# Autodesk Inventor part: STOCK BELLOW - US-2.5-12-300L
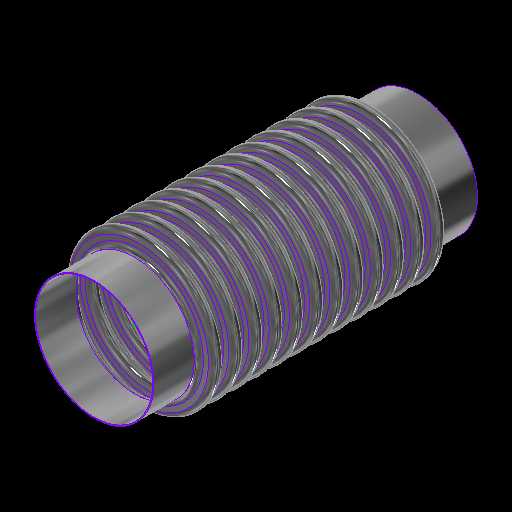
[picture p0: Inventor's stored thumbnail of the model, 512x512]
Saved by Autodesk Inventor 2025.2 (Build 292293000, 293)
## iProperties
Category: 24 GA (0.024 THICK)
RuleStatus: InUse
Created: 2024-01
Part Number: STOCK BELLOW - US-2.5-12-300L
Project: =STOCK BELLOWS: <Stock Number><SFILL>
Material: ASTM A240-304
Description: =STOCK BELLOWS: <Stock Number>, <SID_> I.D., <SOD_> O.D., <SPLY_> PLY, <Category>, <SNET_CONS> CONS.<PITCH_><STANGENT_> TANGENT<SFILL>
Document SubType Name: Sheet Metal
Designer: GS
Stock Number: U.S-2.5-12-300L
Surface Area: 1910.87 cm^2
Volume: 57.9833 cm^3
Sheet Metal Rule: Default
Appearance: STAINLESS STEEL
Mass: 467.188 g
Density: 8.05729 g/cm^3
THK: 0.036
ID: 3.500
OD: 4.250
CONS_: 2
PITCH: 0.500
TANGENT: 0.500
BELLOWS_UPSET: 0.000
d79: 1.000
d82: 1.000
d83: 26.000
d84: 24.000
d174: 8
d214: 8
STHK_: 0.024
SID_: 2.900
SOD_: 3.700
SPITCH_: 0.500
STANGENT__: 1.000
SBELLOWS_UPSET_: 0.000
SDIFF_TAN: 1.000
d252: 2
d275: 2
d287: 0.050
d289: 0.500
d290: 0.000
SOD_NECK: 2 15/16
PLY: 1
PSET: 4.178
PBAR: 1.035
COUNTER: 1.500
NET_TUBE: 3.071
CONS: 2
S_CONS: 0
NET_CONS: 2
ID_M: 88.90 mm
OD_M: 107.95 mm
THK_M: 0.91 mm
ID_U: 3.500 in
OD_U: 4.250 in
THK_U: 0.036 in
TANGENT2: 0.500
TAN_TO_TAN: 1.000 in
d80: 2.571
d81: 10
SID: 2.375
SCONS_: 12
SPITCH: 0.250
STANGENT_: 1.000
SBELLOWS_UPSET: 0.000
SNET_CONS: 12
SS_CONS: 0
SCONS: 8
d190: 8
d191: 1
d192: 1
d193: 8
d194: 0
SIZE: 2.50
PRESSURE: 300
d230: 8
STANGENT: 4.000
SPLY_: 1
d233: 8
d234: 0
d263: 2
d265: 1
d268: 2
d269: 0
d286: 2
d288: 1
d291: 2
d292: 0
SREROLL: 0.750
BLETP: 1.000 ul
PRES_Copy: 85
MATTABLE: 20 GA (0.036 THICK)
PART_NUMBER: U.S-2.5-12-300L
PITCH_: =, <SPITCH_> PITCH,
CFILL: .
SFILL: .
MESH: ,
COMP: 0.89
EXT: 0.45
LAT: 0.52
ANG: 573
ASR: 961
LSR: 436
ANSR: 35
PRES: 300
COMPM: 8.9
EXTM: 4.45
LATM: 5.20
ASRM: 168.300
PRESM: 20.684
LSRM: 76.357
ANSRM: 6.13
TEMPMIN: 20
TEMPMAX: 800
TEMPMINM: -7
TEMPMAXM: 427
WEIGHTM: 0.467
WEIGHT: 1.030
Author: GS
Keywords: 20 GA (0.036 THICK)
Comments: =STOCK BELLOW - <STOCK NUMBER>
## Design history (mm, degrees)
sketch "Sketch2"
  geometry: L1 (0, -177.245)-(0, 562.856) reference; L2 (45.364, 0)-(44.45, 0); L3 (48.082, -2.718)-(50.343, -2.718); L4 (48.082, -3.632)-(50.343, -3.632); L5 (50.343, -9.982)-(48.082, -9.982); L6 (50.343, -9.068)-(48.082, -9.068); L7 (45.364, -12.7)-(44.45, -12.7); L8 (48.082, 0)-(48.082, -12.7); L9 (50.343, -6.35)-(53.975, -6.35); L10 (44.45, 0)-(44.45, -12.7); L11 (20.376, 102.841)-(20.376, 101.926); L12 (58.262, 457.127)-(58.262, 349.177); L13 (58.262, 444.427)-(58.262, 336.477); L14 (93.133, -58.817)-(93.133, -71.517); L15 (118.746, -66.401)-(118.746, -66.401); L16 (50.343, -9.068)-(50.343, -9.982); L17 (48.082, -9.068)-(48.082, -9.982); L18 (48.082, -9.525)-(50.343, -9.525); L19 (53.975, 0)-(53.975, -12.7); L20 (-50.343, -9.068)-(-50.343, -9.982); L21 (-50.343, -2.718)-(-48.082, -2.718); L22 (-50.343, -3.632)-(-48.082, -3.632); L23 (-48.082, -9.068)-(-50.343, -9.068); L24 (-50.343, -9.525)-(-48.082, -9.525); L25 (-48.082, -9.982)-(-50.343, -9.982); L26 (-48.082, -9.068)-(-48.082, -9.982); L27 (-44.45, 0.653)-(-44.45, -12.047); L28 (-48.082, -6.35)-(-44.45, -6.35); L29 (-50.343, 0.653)-(-50.343, -12.7); L30 (-53.061, 0)-(-53.975, 0); L31 (-53.975, 0)-(-53.975, -12.7); L32 (-53.061, -12.7)-(-53.975, -12.7); A1 r 2.718 centre (48.082, 0) between (45.364, 0) and (48.082, -2.718); A2 r 3.632 centre (48.082, 0) between (44.45, 0) and (48.082, -3.632); A3 r 3.632 centre (50.343, -6.35) between (50.343, -9.982) and (50.343, -2.718); A4 r 2.718 centre (50.343, -6.35) between (50.343, -9.068) and (50.343, -3.632); A5 r 2.718 centre (48.082, -12.7) between (48.082, -9.982) and (45.364, -12.7); A6 r 3.632 centre (48.082, -12.7) between (48.082, -9.068) and (44.45, -12.7); A7 r 3.175 centre (50.343, -6.35) between (50.343, -9.525) and (53.518, -6.35); A8 r 3.175 centre (48.082, -12.7) between (48.082, -9.525) and (44.907, -12.7); A9 r 2.718 centre (-50.343, -12.7) between (-50.343, -9.982) and (-53.061, -12.7); A10 r 2.718 centre (-48.082, -6.35) between (-48.082, -9.068) and (-48.082, -3.632); A11 r 3.175 centre (-48.082, -6.35) between (-48.082, -9.525) and (-44.907, -6.35); A12 r 3.632 centre (-48.082, -6.35) between (-48.082, -9.982) and (-48.082, -2.718); A13 r 3.175 centre (-50.343, -12.7) between (-50.343, -9.525) and (-53.518, -12.7); A14 r 3.632 centre (-50.343, -12.7) between (-50.343, -9.068) and (-53.975, -12.7); A15 r 2.718 centre (-50.343, 0) between (-53.061, 0) and (-50.343, -2.718); A16 r 3.632 centre (-50.343, 0) between (-53.975, 0) and (-50.343, -3.632); 10 further points
  constraints: 62 end point, 38 point on circle, 20 tangent, 16 centre point, 12 parallel, 9 midpoint, 7 vertical, 6 coincident, 6 concentric, 6 point on line, 4 equal radius, 4 perpendicular, 3 horizontal, 1 collinear, 1 horizontal alignment, 10 other
  dimensions: "THK" = 0.9144 distance of L11.start L11.end; "ID" = 88.9 distance of L11.end point (20.376, 13.026); "OD" = 107.95 distance of L12.start L12.end; "PITCH" = 12.7 distance of L12.start L13.start; "TANGENT" = 12.7 distance of L14.start L14.end; "BELLOWS_UPSET" = 0 distance of L15.start L15.end; "d43" = 88.9 diameter of L10 L1 (= ID); "d44" = 107.95 diameter of L9.end L1 (= OD); "d45" = 0.9144 distance between parallel lines of L5 L6 (computed from THK, PLY); "d46" = 3.6322 radius of A3 (computed from PITCH, THK, PLY); "UPSET_PITCH" = 12.7 distance of L2.end L7.end (derived); "SIDEWALL_ANGLE" = 360 deg dimension on L3 L9 (derived); "CON_GAP" = 5.4356 distance of point (48.082, -9.068) point (48.082, -3.632) (derived); "TAN1" = 4.98728 dimension on A8 (derived); "TAN2" = 4.98728 dimension on A7 (derived); "LEG1" = 2.2606 distance of L18.start L18.end (derived); "d278" = 0.9144 distance between parallel lines of L25 L23 (derived); "d279" = 3.6322 radius of A12 (derived); "d280" = 12.7 distance of L30.end L31.end (derived); "d281" = 360 deg dimension on L21 L28 (derived); "d282" = 5.4356 distance of point (-50.343, -9.068) point (-50.343, -3.632) (derived); "d283" = 4.98728 dimension on A13 (derived); "d284" = 4.98728 dimension on A11 (derived); "d285" = 2.2606 distance of L24.start L24.end (derived); "d293" = 88.9 diameter of L27 L1 (derived); "d294" = 107.95 diameter of L31 L1 (derived)
  node "Sketch Rectangular Pattern1" dims "d31" = 25.4, "ID" = 88.9
  node "Sketch Rectangular Pattern2" dims "d39" = 25.4, "PITCH" = 12.7
revolve "CONS" stored, may be unused: angle "d48" = 90 deg
node "BELLOW MIDPLANE"
pattern_linear "Rectangular Pattern2" dims "d52" = 12.7 (= UPSET_PITCH)
sketch "Sketch5"
  geometry: C1 r 45.364 at (0, 0) reference; C2 r 44.45 at (0, 0) reference
extrude "TANGENT" new body sketch "Sketch5" distance "d53" = 12.7 (= TANGENT); taper "d54" = 0 deg
revolve "SAMETAN" stored, may be unused: angle "d65" = 90 deg
revolve "DIFFTAN" stored, may be unused: angle "d70" = 90 deg
sketch "Sketch9"
  geometry: L1 (53.319, 0)-(-53.319, 0) reference; L2 (0, -17.78)-(0, 17.78) reference; L3 (38.085, 0)-(-38.085, 0); L4 (38.085, -11.906)-(38.085, 11.906); L5 (25.385, -11.906)-(25.385, 11.906); L6 (13.15, 11.906)-(13.15, -11.906); L7 (-25.385, -11.906)-(-25.385, 11.906); L8 (-38.085, -11.906)-(-38.085, 11.906); L9 (37.291, -11.906)-(37.291, 11.906); L10 (38.085, -11.906)-(37.291, -11.906); L11 (38.085, 11.906)-(37.291, 11.906); L12 (13.546, 11.906)-(12.753, 11.906); L13 (12.753, 11.906)-(12.753, -11.906); L14 (12.753, -11.906)-(13.546, -11.906); L15 (13.546, -11.906)-(13.546, 11.906); L16 (-13.546, 11.906)-(-13.546, -11.906); L17 (-13.15, 11.906)-(-13.15, -11.906); L18 (-13.546, -11.906)-(-12.753, -11.906); L19 (-12.753, -11.906)-(-12.753, 11.906); L20 (-12.753, 11.906)-(-13.546, 11.906); L21 (-38.085, -11.906)-(-37.291, -11.906); L22 (-37.291, -11.906)-(-37.291, 11.906); L23 (-37.291, 11.906)-(-38.085, 11.906); L24 (-38.085, 11.906)-(-38.085, -11.906); L25 (38.085, -0.397)-(-38.085, -0.397); L26 (-38.085, -0.397)-(-38.085, 0.397); L27 (-38.085, 0.397)-(38.085, 0.397); L28 (38.085, 0.397)-(38.085, -0.397); L29 (-38.085, 11.906)-(38.085, 11.906); L30 (38.085, 11.906)-(38.085, 12.7); L31 (38.085, 12.7)-(-38.085, 12.7); L32 (-38.085, 12.7)-(-38.085, 11.906); L33 (38.085, -11.906)-(-38.085, -11.906); L34 (-38.085, -11.906)-(-38.085, -12.7); L35 (-38.085, -12.7)-(38.085, -12.7); L36 (38.085, -12.7)-(38.085, -11.906); 30 further points
  constraints: 68 end point, 13 midpoint, 13 parallel, 8 horizontal, 7 perpendicular, 6 equal length, 3 point on line, 2 vertical, 14 other
  dimensions: "d115" = 23.8125 distance of L4.start L4.end (derived); "d116" = 12.7 distance between parallel lines of L4 L5 (derived); "d117" = 12.23516 distance between parallel lines of L5 L6 (derived); "d125" = 38.53427 distance between parallel lines of L7 L6 (derived); "d127" = 12.7 distance between parallel lines of L8 L7 (derived); "d128" = 24.93516 distance between parallel lines of L6 L4 (derived); "d130" = 76.16943 distance between parallel lines of L8 L4 (derived); "RULER_THK" = 0.79375 distance between parallel lines of L4 L9; "d135" = 0.79375 distance of L13.end L14.end (derived); "d138" = 26.29911 distance of L13.end L16.end (derived); "d143" = 0.79375 distance of L22.end L8.end (derived); "d144" = 0.79375 distance between parallel lines of L27 L25 (derived)
extrude "RULER" join sketch "Sketch9" distance "d149" = 0.79375 (derived); taper "d150" = 0 deg
extrude "BARS" join sketch "Sketch9" distance "d151" = 0.79375 (derived); taper "d152" = 0 deg
pattern_linear "Rectangular Pattern4" dims "d155" = 26.29911 (derived)
sketch "Sketch13"
  geometry: L1 (93.149, -52.467)-(93.149, -77.867); L2 (37.44, 0)-(36.83, 0); L3 (37.44, -12.7)-(36.83, -12.7); L4 (43.51, -9.83)-(40.31, -9.83); L5 (43.51, -9.22)-(40.31, -9.22); L6 (43.51, -6.35)-(46.99, -6.35); L7 (40.31, -2.87)-(43.51, -2.87); L8 (40.31, 0)-(40.31, -12.7); L9 (36.83, 0)-(36.83, -12.7); L10 (58.254, -402.451)-(58.254, -496.431); L11 (58.254, -415.151)-(58.254, -509.131); L12 (58.254, -440.551)-(58.254, -534.531); L13 (58.254, -453.251)-(58.254, -547.231); L14 (58.254, -465.951)-(58.254, -559.931); L15 (58.254, -478.651)-(58.254, -572.631); L16 (58.254, -491.351)-(58.254, -585.331); L17 (58.254, -427.851)-(58.254, -521.831); L18 (20.376, 102.536)-(20.376, 101.926); L19 (40.31, -3.48)-(43.51, -3.48); L20 (0, -722.904)-(0, 240.109) reference; L21 (-23.752, 0)-(142.514, 0) reference; A1 r 2.87 centre (40.31, 0) between (37.44, 0) and (40.31, -2.87); A2 r 2.87 centre (40.31, -12.7) between (40.31, -9.83) and (37.44, -12.7); A3 r 3.48 centre (40.31, -12.7) between (40.31, -9.22) and (36.83, -12.7); A4 r 2.87 centre (43.51, -6.35) between (43.51, -9.22) and (43.51, -3.48); A5 r 3.48 centre (43.51, -6.35) between (43.51, -9.83) and (43.51, -2.87); A6 r 3.48 centre (40.31, 0) between (36.83, 0) and (40.31, -3.48); 6 further points; 1 other entity
  constraints: 38 end point, 15 point on circle, 9 tangent, 6 centre point, 6 parallel, 5 vertical alignment, 4 point on line, 4 vertical, 3 coincident, 3 concentric, 2 collinear, 2 equal radius, 1 horizontal, 1 perpendicular, 23 other
  dimensions: "SBELLOWS_UPSET_" = 0 distance of point (118.762, -66.401) point (118.762, -66.401); "STOTAL_THK_BELLOW__" = 0.6096 distance between parallel lines of L4 L5 (derived); "d224" = 3.4798 radius of A5 (derived); "d225" = 12.7 distance of L2.end L3.end (derived); "SSIDEWALL_ANGLE_" = 0 deg angle of L7 L6 (derived); "SSCON_GAP_" = 5.7404 distance of point (40.31, -9.22) point (40.31, -3.48) (derived); "d235" = 73.66 diameter of L9 L20 (derived); "d236" = 93.98 diameter of L6.end L20 (derived)
  node "Sketch Rectangular Pattern4" dims "d228" = 25.4
  node "Sketch Rectangular Pattern5" dims "d229" = 25.4
revolve "SBELLOW" stored, may be unused: angle "d197" = 90 deg
pattern_linear "Rectangular Pattern5" dims "d204" = 12.7 (derived)
revolve "STANGENT" stored, may be unused: angle "d240" = 90 deg
revolve "SSAMETAN" stored, may be unused: angle "d241" = 90 deg
revolve "SDIFFTAN" stored, may be unused: angle "d246" = 90 deg
revolve "INVCON" stored, may be unused: angle "d295" = 90 deg
pattern_linear "Rectangular Pattern6" dims "d298" = 12.7 (derived)
revolve "INVTANGENT" stored, may be unused: angle "d302" = 90 deg
revolve "INVSAMETAN" stored, may be unused: angle "d307" = 90 deg
revolve "INVDIFFTAN" stored, may be unused: angle "d312" = 90 deg
sketch "ID BELLOW MOUNT CALC"
  geometry: L1 (44.45, 0)-(38.1, 0); L2 (38.1, 0)-(38.1, 12.7); L3 (38.1, 12.7)-(44.45, 12.7); L4 (44.45, 12.7)-(44.45, 0); L5 (36.513, 12.7)-(35.598, 12.7); L6 (35.598, 12.7)-(35.598, 0); L7 (35.598, 0)-(36.513, 0); L8 (36.513, 0)-(36.513, 12.7); L9 (0, -2.54)-(0, 15.24) reference; L10 (-8.89, 0)-(53.34, 0) reference; 1 further point
  constraints: 16 end point, 5 parallel, 2 collinear, 2 horizontal, 2 perpendicular
  dimensions: "d314" = 12.7 distance of L5.end L6.end (derived); "d315" = 0.9144 distance of L5.start L5.end (derived); "IG" = 1.5875 distance between parallel lines of L2 L8; "PIPE_OD" = 88.9 diameter of L4 L9; "PIPE_WALL" = 6.35 distance of L2.end L3.end; "ID_MT_BELLOW" = 71.1962 diameter of L6 L9 (derived)
revolve "CFILL" stored, may be unused: angle "d320" = 90 deg
pattern_linear "Rectangular Pattern7" dims "d323" = 12.7 (derived)
revolve "SFILL" stored, may be unused: angle "d324" = 90 deg
pattern_linear "Rectangular Pattern8" dims "d327" = 12.7 (derived)
node "STOCK BELLOW MIDPLANE"
node "BELLOW"
sketch "Sketch6"
  geometry: L1 (-12.7, 45.364)-(0, 45.364); L2 (0, 45.364)-(0, 44.45); L3 (0, 44.45)-(-12.7, 44.45); L4 (-12.7, 44.45)-(-12.7, 45.364); L5 (10.16, 0)-(-60.96, 0) reference; L6 (-38.1, -89.422)-(-38.1, 153.44) reference; 1 further point
  constraints: 8 end point, 2 parallel, 1 horizontal, 1 perpendicular
  dimensions: "d61" = 12.7 distance of L2.end L3.end (derived); "d62" = 0.9144 distance of L1.end L2.end (derived); "d63" = 88.9 diameter of L3 L5 (derived); "d64" = 25.4 distance between parallel lines of L4 L6 (derived)
sketch "Sketch12"
  geometry: 1 further point
sketch "Sketch14"
  geometry: L1 (-25.4, 37.44)-(0, 37.44); L2 (0, 37.44)-(0, 36.83); L3 (0, 36.83)-(-25.4, 36.83); L4 (-25.4, 36.83)-(-25.4, 37.44); L5 (5.08, 0)-(-30.48, 0) reference; L6 (0, -8.89)-(0, 53.34) reference; 1 further point
  constraints: 8 end point, 2 parallel, 1 collinear, 1 horizontal, 1 perpendicular
  dimensions: "d237" = 0.6096 distance of L3.end L1.start (derived); "d238" = 73.66 diameter of L3 L5 (derived); "d239" = 25.4 distance of L1.start L1.end (derived); "SOD_NECK" = 74.8792 diameter of L1 L5 (derived)
sketch "Sketch15"
  geometry: L1 (-8.89, 0)-(53.34, 0) reference; L2 (36.83, -152.4)-(37.44, -152.4); L3 (37.44, -152.4)-(37.44, -177.8); L4 (37.44, -177.8)-(36.83, -177.8); L5 (36.83, -177.8)-(36.83, -152.4); L6 (0, -215.9)-(0, 50.8) reference; 1 further point
  constraints: 8 end point, 2 parallel, 1 horizontal, 1 perpendicular
  dimensions: "d205" = 25.4 distance of L4.end L2.start (derived); "d206" = 0.6096 distance of L3.end L4.end (derived); "d207" = 73.66 diameter of L5 L6 (derived); "d208" = 152.4 distance between parallel lines of L1 L2 (derived)
node "TANGENT_"
node "SAME_TAN"
sketch "Sketch8"
  geometry: L1 (45.364, -25.4)-(44.45, -25.4); L2 (44.45, -25.4)-(44.45, -38.1); L3 (44.45, -38.1)-(45.364, -38.1); L4 (45.364, -38.1)-(45.364, -25.4); L5 (0, -48.26)-(0, 22.86) reference; L6 (-89.422, 0)-(153.44, 0) reference; 1 further point
  constraints: 8 end point, 2 parallel, 1 horizontal, 1 perpendicular
  dimensions: "d66" = 88.9 diameter of L2 L5 (derived); "TOTAL_THK_BELLOW" = 0.9144 distance of L2.end L3.end (derived); "d68" = 25.4 distance between parallel lines of L1 L6 (derived); "d69" = 12.7 distance of L1.end L2.end (derived)
node "DIFF_TAN"
node "Sketch Rectangular Pattern3" dims "d138" = 26.29911 (derived), "d141" = 25.4
node "SBELLOW_"
node "STANGENT_"
node "SSAME_TAN"
sketch "Sketch16"
  geometry: L1 (37.44, -152.4)-(36.83, -152.4); L2 (36.83, -152.4)-(36.83, -177.8); L3 (36.83, -177.8)-(37.44, -177.8); L4 (37.44, -177.8)-(37.44, -152.4); L5 (0, -215.9)-(0, 50.8) reference; L6 (-8.89, 0)-(53.34, 0) reference; 1 further point
  constraints: 8 end point, 2 parallel, 1 horizontal, 1 perpendicular
  dimensions: "SDIFF_TAN" = 25.4 distance of L3.end L1.start; "d243" = 0.6096 distance of L2.end L3.end (derived); "d244" = 152.4 distance between parallel lines of L1 L6 (derived); "d245" = 73.66 diameter of L2 L5 (derived)
node "SDIFF_TAN"
body "Solid15"
sketch "Sketch17"
  geometry: L1 (53.975, 12.7)-(53.061, 12.7); L2 (53.061, 12.7)-(53.061, 0); L3 (53.061, 0)-(53.975, 0); L4 (53.975, 0)-(53.975, 12.7); L5 (0, -2.54)-(0, 15.24) reference; L6 (-10.795, 0)-(64.77, 0) reference; 2 further points
  constraints: 8 end point, 2 parallel, 1 horizontal, 1 midpoint, 1 perpendicular, 1 point on line
  dimensions: "INVTANGENT" = 12.7 distance of L3.end L1.start (derived); "d300" = 0.9144 distance of L1.start L1.end (derived); "d301" = 107.95 diameter of L4 L5 (derived)
body "Solid16"
sketch "Sketch18"
  geometry: L1 (53.975, -25.4)-(53.061, -25.4); L2 (53.061, -25.4)-(53.061, -38.1); L3 (53.061, -38.1)-(53.975, -38.1); L4 (53.975, -38.1)-(53.975, -25.4); L5 (-10.795, 0)-(64.77, 0) reference; L6 (0, -48.26)-(0, 22.86) reference; 1 further point
  constraints: 8 end point, 2 parallel, 1 horizontal, 1 perpendicular
  dimensions: "d303" = 25.4 distance between parallel lines of L1 L5 (derived); "d304" = 12.7 distance of L3.end L1.start (derived); "d305" = 0.9144 distance of L2.end L3.end (derived); "d306" = 107.95 diameter of L4 L6 (derived)
body "Solid17"
sketch "Sketch19"
  geometry: L1 (53.975, -25.4)-(53.061, -25.4); L2 (53.061, -25.4)-(53.061, -38.1); L3 (53.061, -38.1)-(53.975, -38.1); L4 (53.975, -38.1)-(53.975, -25.4); L5 (0, -48.26)-(0, 22.86) reference; L6 (-10.795, 0)-(64.77, 0) reference; 1 further point
  constraints: 8 end point, 2 parallel, 1 horizontal, 1 perpendicular
  dimensions: "d308" = 12.7 distance of L1.end L2.end (derived); "d309" = 107.95 diameter of L4 L5 (derived); "d310" = 0.9144 distance of L2.end L3.end (derived); "d311" = 25.4 distance between parallel lines of L1 L6 (derived)
body "Solid18"
body "Solid19"
body "Solid20"
other parameters: "BMPL" = -76.2, "PSET" = 106.1212 (computed from OD, THK, PLY) [user parameter], "PBAR" = 26.29911 (= 0.570796 x PITCH + OD - ID) [user parameter; used in 1 equation term], "COUNTER" = 15 [user parameter], "NET_TUBE" = 77.99823 (computed from CONS_, PBAR, TANGENT) [user parameter], "S_CONS" = 0 [user parameter; used in 1 equation term], "ID_M" = 88.9 (= ID) [user parameter], "OD_M" = 107.95 (= OD) [user parameter], "THK_M" = 0.9144 (= THK) [user parameter], "ID_U" = 88.9 (= ID) [user parameter], "OD_U" = 107.95 (= OD) [user parameter], "THK_U" = 0.9144 (= THK) [user parameter], "D_UNITS" = 0 [user parameter], "TANGENT2" = 12.7 [user parameter], "TAN_TO_TAN" = 25.4 [user parameter], "OD_NECK" = 90.7288 [user parameter], "d79" = 25.4, "d80" = 65.29823 [user parameter], "d82" = 25.4, "d83" = 660.4, "d84" = 609.6, "sa_0" = 4, "FRAME_THK" = 0.79375 [user parameter], "CON_FLAT" = 12.23516 [user parameter], "SID" = 60.325 [user parameter], "SPITCH" = 6.35 [user parameter], "STANGENT_" = 25.4 [user parameter], "SBELLOWS_UPSET" = 0 [user parameter], "SS_CONS" = 0 [user parameter], "STAN_TO_TAN_" = 152.4 [user parameter], "d100" = 0.6096 [user parameter], "d191" = 25.4 [user parameter], "d194" = 0 [user parameter], "STANGENT" = 101.6 [user parameter], "d234" = 0 [user parameter], "SUPSET_PITCH_" = 12.7 [user parameter], "d269" = 0 [user parameter], "d287" = 1.27, "d289" = 12.7, "d290" = 0, "d292" = 0 [user parameter], "Thickness" = 3.048 (derived), "KFactor" = 4.4, "BendRadius" = 3.048 (derived), "BendReliefWidth" = 3.048 (derived), "BendReliefDepth" = 1.524 (derived), "CornerReliefSize" = 12.192 (derived), "SeamGap" = 0.00508, "MinimumRemnant" = 6.096 (derived), "TransitionRadius" = 3.048 (derived), "JacobiRadiusSize" = 3.048 (derived), "GapSize" = 3.048 (derived), "SREROLL" = 19.05 [user parameter], "CUR_STK_PITCH" = 12.7 [user parameter], "d328" = -76.2 (derived), "BLETP" = 1 [user parameter], "ASRM" = 1682.9993 [user parameter], "PRESM" = 206.83949 [user parameter], "LSRM" = 763.5668 [user parameter], "ANSRM" = 61.2955 [user parameter], "TEMPMIN" = 2664.83333 [user parameter], "TEMPMAX" = 6998.16667 [user parameter], "TEMPMINM" = 2664.83333 [user parameter], "TEMPMAXM" = 6998.16667 [user parameter], "WEIGHT" = 4.67188 [user parameter], "WEIGHTM" = 0.00467 [user parameter]
